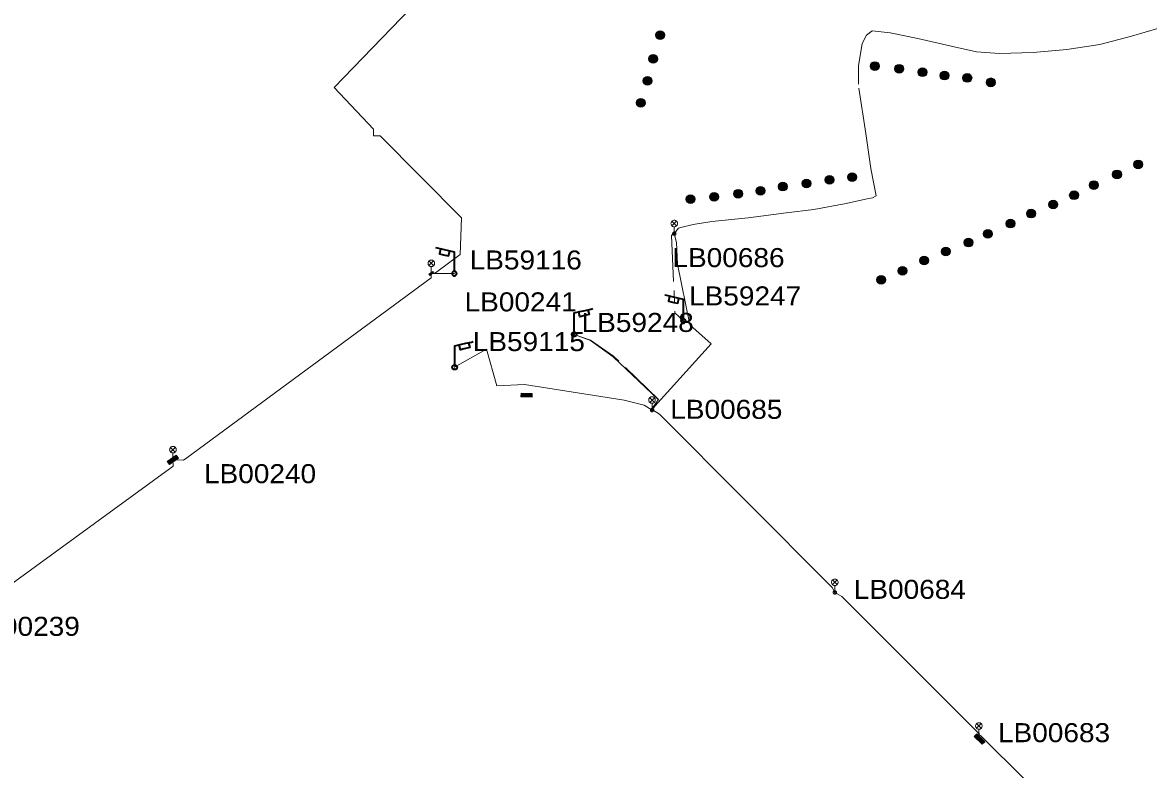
# Model space of a CAD drawing. Extents: x -688049 to -687261, y -973611 to -973038.
# Drawn here: x -687682.8 to -687554.6, y -973468.5 to -973383.4 of the extents above; entities that cross this region are included whole.
import ezdxf

# ---------------------------------------------------------------- set-up
doc = ezdxf.new("R2010")
doc.units = 0
doc.header["$LTSCALE"] = 0.87
doc.linetypes.add('LONG_DASH_SHORT_DASH', pattern=[9.9, 6, -1.2, 1.5, -1.2])
doc.linetypes.add('LONG_DASHED', pattern=[7.5, 6, -1.5])
doc.layers.add('1', color=7, linetype='Continuous', lineweight=13)

msp = doc.modelspace()

# ---------------------------------------------------------------- hatches: boundary and pattern name
at = {"layer": '1'}
for points in [[(-687610.051, -973385.316, 1), (-687610.35, -973384.372, 1)], [(-687610.844, -973388.007, 1), (-687611.143, -973387.063, 1)], [(-687585.608, -973388.841, 1), (-687585.907, -973387.896, 1)], [(-687582.831, -973389.138, 1), (-687583.13, -973388.194, 1)], [(-687580.194, -973389.545, 1), (-687580.493, -973388.601, 1)], [(-687577.677, -973389.928, 1), (-687577.976, -973388.984, 1)], [(-687575.088, -973390.19, 1), (-687575.387, -973389.246, 1)], [(-687611.485, -973390.519, 1), (-687611.784, -973389.574, 1)], [(-687572.426, -973390.694, 1), (-687572.725, -973389.749, 1)], [(-687612.25, -973393.017, 1), (-687612.549, -973392.072, 1)], [(-687555.641, -973400.036, 1), (-687555.94, -973399.092, 1)], [(-687590.78, -973401.793, 1), (-687591.079, -973400.849, 1)], [(-687588.186, -973401.491, 1), (-687588.485, -973400.546, 1)], [(-687558.051, -973401.176, 1), (-687558.35, -973400.232, 1)], [(-687598.621, -973403.047, 1), (-687598.92, -973402.103, 1)], [(-687596.084, -973402.573, 1), (-687596.382, -973401.628, 1)], [(-687593.401, -973402.217, 1), (-687593.699, -973401.273, 1)], [(-687560.679, -973402.389, 1), (-687560.978, -973401.444, 1)], [(-687606.599, -973403.992, 1), (-687606.898, -973403.047, 1)], [(-687603.915, -973403.733, 1), (-687604.214, -973402.789, 1)], [(-687601.184, -973403.377, 1), (-687601.483, -973402.433, 1)], [(-687562.944, -973403.558, 1), (-687563.243, -973402.613, 1)], [(-687567.837, -973405.645, 1), (-687568.136, -973404.701, 1)], [(-687565.306, -973404.601, 1), (-687565.605, -973403.657, 1)], [(-687570.175, -973406.785, 1), (-687570.474, -973405.841, 1)], [(-687572.754, -973407.949, 1), (-687573.053, -973407.005, 1)], [(-687574.948, -973408.945, 1), (-687575.246, -973408, 1)], [(-687577.527, -973409.966, 1), (-687577.826, -973409.021, 1)], [(-687580.008, -973410.99, 1), (-687580.307, -973410.046, 1)], [(-687635.974, -973411.887), (-687636.396, -973412.214), (-687636.505, -973412.073), (-687636.083, -973411.747)], [(-687636.102, -973411.896), (-687636.356, -973412.092), (-687636.377, -973412.064), (-687636.124, -973411.868)], [(-687584.892, -973413.189, 1), (-687585.191, -973412.245, 1)], [(-687582.471, -973412.165, 1), (-687582.77, -973411.221, 1)], [(-687624.773, -973426.072), (-687626.038, -973426.054), (-687626.032, -973425.632), (-687624.767, -973425.65)], [(-687625.024, -973425.9), (-687625.783, -973425.889), (-687625.782, -973425.805), (-687625.022, -973425.815)], [(-687665.014, -973433.008), (-687666.038, -973433.752), (-687666.286, -973433.411), (-687665.262, -973432.666)], [(-687665.318, -973433.02), (-687665.932, -973433.467), (-687665.982, -973433.398), (-687665.368, -973432.952)], [(-687574.161, -973464.421), (-687573.26, -973465.31), (-687573.556, -973465.61), (-687574.457, -973464.722)], [(-687574.099, -973464.719), (-687573.558, -973465.252), (-687573.618, -973465.312), (-687574.158, -973464.779)]]:
    msp.add_hatch(color=256, dxfattribs=at).paths.add_polyline_path(points)

# ---------------------------------------------------------------- linework, layer by layer
for p, q in [((-687608.855, -973406.035), (-687608.325, -973406.565)), ((-687608.855, -973406.565), (-687608.325, -973406.035)), ((-687608.59, -973407.45), (-687608.59, -973406.675)), ((-687636.505, -973410.565), (-687635.975, -973411.095)), ((-687636.505, -973411.095), (-687635.975, -973410.565)), ((-687636.24, -973411.98), (-687636.24, -973411.205)), ((-687611.385, -973426.135), (-687610.855, -973426.665)), ((-687611.385, -973426.665), (-687610.855, -973426.135)), ((-687611.12, -973427.55), (-687611.12, -973426.775)), ((-687665.915, -973431.795), (-687665.385, -973432.325)), ((-687665.915, -973432.325), (-687665.385, -973431.795)), ((-687665.65, -973433.21), (-687665.65, -973432.435)), ((-687590.585, -973446.895), (-687590.055, -973447.425)), ((-687590.585, -973447.425), (-687590.055, -973446.895)), ((-687590.32, -973448.31), (-687590.32, -973447.535)), ((-687574.185, -973463.255), (-687573.655, -973463.785)), ((-687574.185, -973463.785), (-687573.655, -973463.255)), ((-687573.92, -973464.67), (-687573.92, -973463.895))]:
    msp.add_line(p, q, dxfattribs=at)
at = {"layer": '1', "linetype": 'LONG_DASHED'}
msp.add_line((-687636.24, -973411.98), (-687633.616, -973411.993), dxfattribs=at)
at = {"layer": '1', "lineweight": 35}
for p, q in [((-687633.589, -973411.993), (-687633.643, -973411.993)), ((-687607.523, -973417.39), (-687607.577, -973417.39)), ((-687620.007, -973418.92), (-687619.953, -973418.92)), ((-687633.606, -973422.675), (-687633.552, -973422.675))]:
    msp.add_line(p, q, dxfattribs=at)
at = {"layer": '1'}
for points in [[(-687635.62, -973366.14), (-687635.225, -973365.919), (-687633.134, -973366.526), (-687636.395, -973379.478), (-687647.285, -973390.792), (-687642.829, -973395.545), (-687642.829, -973396.299), (-687642.074, -973396.299), (-687632.804, -973405.662), (-687632.954, -973409.811), (-687635.757, -973411.904), (-687636.24, -973411.98)], [(-687611.12, -973427.55), (-687610.797, -973427.086), (-687604.393, -973420.018), (-687606.807, -973417.83), (-687608.216, -973410.947), (-687608.337, -973408.473), (-687608.59, -973407.45)], [(-687636.24, -973411.98), (-687636.24, -973412.467), (-687664.079, -973432.966), (-687664.457, -973433.245), (-687665.65, -973433.21)], [(-687619.98, -973418.92), (-687618.115, -973419.615), (-687615.548, -973421.498), (-687610.435, -973426.34), (-687611.12, -973427.55)], [(-687611.12, -973427.55), (-687612.029, -973427.002), (-687614.309, -973426.435), (-687625.62, -973424.619), (-687628.769, -973424.779), (-687629.963, -973420.617), (-687633.597, -973422.675)], [(-687611.085, -973427.515), (-687610.257, -973428.003), (-687590.631, -973447.734), (-687590.299, -973448.319)], [(-687665.65, -973433.21), (-687665.607, -973433.919), (-687690.297, -973451.9), (-687691.35, -973452.06)], [(-687590.299, -973448.319), (-687589.534, -973448.773), (-687573.855, -973464.45), (-687573.92, -973464.67)], [(-687573.92, -973464.67), (-687573.727, -973464.6), (-687563.369, -973474.889), (-687563.105, -973476.008), (-687557.547, -973481.454), (-687555.888, -973481.862), (-687555.339, -973482.791), (-687555.04, -973483.62)]]:
    msp.add_lwpolyline(points, dxfattribs=at)
at = {"layer": '1', "linetype": 'LONG_DASH_SHORT_DASH'}
for points in [[(-687608.55, -973407.38), (-687608.11, -973406.84), (-687607.68, -973406.71), (-687606.43, -973406.41), (-687604.3, -973406.08), (-687600.18, -973405.65), (-687595.86, -973405.09), (-687592.69, -973404.71), (-687589.01, -973404.01), (-687586.83, -973403.53), (-687586.02, -973403.36), (-687585.62, -973403.15), (-687586.23, -973400.05), (-687586.8, -973396.04), (-687587.64, -973390.41), (-687587.64, -973388.33), (-687587.22, -973385.79), (-687586.71, -973384.83), (-687586.07, -973384.34), (-687584, -973384.57), (-687580.87, -973385.24), (-687577.06, -973386.09), (-687574.21, -973386.74), (-687571.58, -973386.94), (-687567.76, -973386.84), (-687563.92, -973386.49), (-687560.14, -973385.9), (-687556.57, -973384.95), (-687553.44, -973384.04)], [(-687608.61, -973407.33), (-687608.89, -973407.68), (-687608.51, -973416.47), (-687607.55, -973417.39)], [(-687611.15, -973427.39), (-687610.39, -973426.34), (-687615.5, -973421.39), (-687618.11, -973419.59), (-687619.98, -973418.92)]]:
    msp.add_lwpolyline(points, dxfattribs=at)
at = {"layer": '1'}
for points in [[(-687608.215, -973406.3), (-687608.221, -973406.235), (-687608.238, -973406.172), (-687608.265, -973406.112), (-687608.303, -973406.059), (-687608.349, -973406.013), (-687608.402, -973405.975), (-687608.462, -973405.948), (-687608.525, -973405.931), (-687608.59, -973405.925), (-687608.655, -973405.931), (-687608.718, -973405.948), (-687608.778, -973405.975), (-687608.831, -973406.013), (-687608.877, -973406.059), (-687608.915, -973406.112), (-687608.942, -973406.172), (-687608.959, -973406.235), (-687608.965, -973406.3), (-687608.959, -973406.365), (-687608.942, -973406.428), (-687608.915, -973406.487), (-687608.877, -973406.541), (-687608.831, -973406.587), (-687608.778, -973406.625), (-687608.718, -973406.652), (-687608.655, -973406.669), (-687608.59, -973406.675), (-687608.525, -973406.669), (-687608.462, -973406.652), (-687608.402, -973406.625), (-687608.349, -973406.587), (-687608.303, -973406.541), (-687608.265, -973406.487), (-687608.238, -973406.428), (-687608.221, -973406.365)], [(-687608.4, -973407.45), (-687608.403, -973407.417), (-687608.411, -973407.385), (-687608.425, -973407.355), (-687608.444, -973407.328), (-687608.468, -973407.304), (-687608.495, -973407.285), (-687608.525, -973407.271), (-687608.557, -973407.263), (-687608.59, -973407.26), (-687608.623, -973407.263), (-687608.655, -973407.271), (-687608.685, -973407.285), (-687608.712, -973407.304), (-687608.736, -973407.328), (-687608.755, -973407.355), (-687608.769, -973407.385), (-687608.777, -973407.417), (-687608.78, -973407.45), (-687608.777, -973407.483), (-687608.769, -973407.515), (-687608.755, -973407.545), (-687608.736, -973407.572), (-687608.712, -973407.596), (-687608.685, -973407.615), (-687608.655, -973407.629), (-687608.623, -973407.637), (-687608.59, -973407.64), (-687608.557, -973407.637), (-687608.525, -973407.629), (-687608.495, -973407.615), (-687608.468, -973407.596), (-687608.444, -973407.572), (-687608.425, -973407.545), (-687608.411, -973407.515), (-687608.403, -973407.483)], [(-687608.54, -973407.45), (-687608.541, -973407.441), (-687608.543, -973407.433), (-687608.547, -973407.425), (-687608.552, -973407.418), (-687608.558, -973407.412), (-687608.565, -973407.407), (-687608.573, -973407.403), (-687608.581, -973407.401), (-687608.59, -973407.4), (-687608.599, -973407.401), (-687608.607, -973407.403), (-687608.615, -973407.407), (-687608.622, -973407.412), (-687608.628, -973407.418), (-687608.633, -973407.425), (-687608.637, -973407.433), (-687608.639, -973407.441), (-687608.64, -973407.45), (-687608.639, -973407.459), (-687608.637, -973407.467), (-687608.633, -973407.475), (-687608.628, -973407.482), (-687608.622, -973407.488), (-687608.615, -973407.493), (-687608.607, -973407.497), (-687608.599, -973407.499), (-687608.59, -973407.5), (-687608.581, -973407.499), (-687608.573, -973407.497), (-687608.565, -973407.493), (-687608.558, -973407.488), (-687608.552, -973407.482), (-687608.547, -973407.475), (-687608.543, -973407.467), (-687608.541, -973407.459)], [(-687635.865, -973410.83), (-687635.871, -973410.765), (-687635.888, -973410.702), (-687635.915, -973410.643), (-687635.953, -973410.589), (-687635.999, -973410.543), (-687636.052, -973410.505), (-687636.112, -973410.478), (-687636.175, -973410.461), (-687636.24, -973410.455), (-687636.305, -973410.461), (-687636.368, -973410.478), (-687636.428, -973410.505), (-687636.481, -973410.543), (-687636.527, -973410.589), (-687636.565, -973410.643), (-687636.592, -973410.702), (-687636.609, -973410.765), (-687636.615, -973410.83), (-687636.609, -973410.895), (-687636.592, -973410.958), (-687636.565, -973411.018), (-687636.527, -973411.071), (-687636.481, -973411.117), (-687636.428, -973411.155), (-687636.368, -973411.182), (-687636.305, -973411.199), (-687636.24, -973411.205), (-687636.175, -973411.199), (-687636.112, -973411.182), (-687636.052, -973411.155), (-687635.999, -973411.117), (-687635.953, -973411.071), (-687635.915, -973411.018), (-687635.888, -973410.958), (-687635.871, -973410.895)], [(-687635.974, -973411.887), (-687636.396, -973412.214), (-687636.505, -973412.073), (-687636.083, -973411.747)], [(-687635.974, -973411.887), (-687636.396, -973412.214), (-687636.505, -973412.073), (-687636.083, -973411.747)], [(-687636.102, -973411.896), (-687636.356, -973412.092), (-687636.377, -973412.064), (-687636.124, -973411.868)], [(-687624.773, -973426.072), (-687626.038, -973426.054), (-687626.032, -973425.632), (-687624.767, -973425.65)], [(-687624.773, -973426.072), (-687626.038, -973426.054), (-687626.032, -973425.632), (-687624.767, -973425.65)], [(-687625.024, -973425.9), (-687625.783, -973425.889), (-687625.782, -973425.805), (-687625.022, -973425.815)], [(-687610.745, -973426.4), (-687610.751, -973426.335), (-687610.768, -973426.272), (-687610.795, -973426.212), (-687610.833, -973426.159), (-687610.879, -973426.113), (-687610.932, -973426.075), (-687610.992, -973426.048), (-687611.055, -973426.031), (-687611.12, -973426.025), (-687611.185, -973426.031), (-687611.248, -973426.048), (-687611.308, -973426.075), (-687611.361, -973426.113), (-687611.407, -973426.159), (-687611.445, -973426.212), (-687611.472, -973426.272), (-687611.489, -973426.335), (-687611.495, -973426.4), (-687611.489, -973426.465), (-687611.472, -973426.528), (-687611.445, -973426.588), (-687611.407, -973426.641), (-687611.361, -973426.687), (-687611.308, -973426.725), (-687611.248, -973426.752), (-687611.185, -973426.769), (-687611.12, -973426.775), (-687611.055, -973426.769), (-687610.992, -973426.752), (-687610.932, -973426.725), (-687610.879, -973426.687), (-687610.833, -973426.641), (-687610.795, -973426.588), (-687610.768, -973426.528), (-687610.751, -973426.465)], [(-687610.93, -973427.55), (-687610.933, -973427.517), (-687610.941, -973427.485), (-687610.955, -973427.455), (-687610.974, -973427.428), (-687610.998, -973427.404), (-687611.025, -973427.385), (-687611.055, -973427.371), (-687611.087, -973427.363), (-687611.12, -973427.36), (-687611.153, -973427.363), (-687611.185, -973427.371), (-687611.215, -973427.385), (-687611.242, -973427.404), (-687611.266, -973427.428), (-687611.285, -973427.455), (-687611.299, -973427.485), (-687611.307, -973427.517), (-687611.31, -973427.55), (-687611.307, -973427.583), (-687611.299, -973427.615), (-687611.285, -973427.645), (-687611.266, -973427.672), (-687611.242, -973427.696), (-687611.215, -973427.715), (-687611.185, -973427.729), (-687611.153, -973427.737), (-687611.12, -973427.74), (-687611.087, -973427.737), (-687611.055, -973427.729), (-687611.025, -973427.715), (-687610.998, -973427.696), (-687610.974, -973427.672), (-687610.955, -973427.645), (-687610.941, -973427.615), (-687610.933, -973427.583)], [(-687611.07, -973427.55), (-687611.071, -973427.541), (-687611.073, -973427.533), (-687611.077, -973427.525), (-687611.082, -973427.518), (-687611.088, -973427.512), (-687611.095, -973427.507), (-687611.103, -973427.503), (-687611.111, -973427.501), (-687611.12, -973427.5), (-687611.129, -973427.501), (-687611.137, -973427.503), (-687611.145, -973427.507), (-687611.152, -973427.512), (-687611.158, -973427.518), (-687611.163, -973427.525), (-687611.167, -973427.533), (-687611.169, -973427.541), (-687611.17, -973427.55), (-687611.169, -973427.559), (-687611.167, -973427.567), (-687611.163, -973427.575), (-687611.158, -973427.582), (-687611.152, -973427.588), (-687611.145, -973427.593), (-687611.137, -973427.597), (-687611.129, -973427.599), (-687611.12, -973427.6), (-687611.111, -973427.599), (-687611.103, -973427.597), (-687611.095, -973427.593), (-687611.088, -973427.588), (-687611.082, -973427.582), (-687611.077, -973427.575), (-687611.073, -973427.567), (-687611.071, -973427.559)], [(-687665.014, -973433.008), (-687666.038, -973433.752), (-687666.286, -973433.411), (-687665.262, -973432.666)], [(-687665.014, -973433.008), (-687666.038, -973433.752), (-687666.286, -973433.411), (-687665.262, -973432.666)], [(-687665.275, -973432.06), (-687665.281, -973431.995), (-687665.298, -973431.932), (-687665.325, -973431.872), (-687665.363, -973431.819), (-687665.409, -973431.773), (-687665.462, -973431.735), (-687665.522, -973431.708), (-687665.585, -973431.691), (-687665.65, -973431.685), (-687665.715, -973431.691), (-687665.778, -973431.708), (-687665.838, -973431.735), (-687665.891, -973431.773), (-687665.937, -973431.819), (-687665.975, -973431.872), (-687666.002, -973431.932), (-687666.019, -973431.995), (-687666.025, -973432.06), (-687666.019, -973432.125), (-687666.002, -973432.188), (-687665.975, -973432.247), (-687665.937, -973432.301), (-687665.891, -973432.347), (-687665.838, -973432.385), (-687665.778, -973432.412), (-687665.715, -973432.429), (-687665.65, -973432.435), (-687665.585, -973432.429), (-687665.522, -973432.412), (-687665.462, -973432.385), (-687665.409, -973432.347), (-687665.363, -973432.301), (-687665.325, -973432.247), (-687665.298, -973432.188), (-687665.281, -973432.125)], [(-687665.318, -973433.02), (-687665.932, -973433.467), (-687665.982, -973433.398), (-687665.368, -973432.952)], [(-687589.945, -973447.16), (-687589.951, -973447.095), (-687589.968, -973447.032), (-687589.995, -973446.972), (-687590.033, -973446.919), (-687590.079, -973446.873), (-687590.133, -973446.835), (-687590.192, -973446.808), (-687590.255, -973446.791), (-687590.32, -973446.785), (-687590.385, -973446.791), (-687590.448, -973446.808), (-687590.508, -973446.835), (-687590.561, -973446.873), (-687590.607, -973446.919), (-687590.645, -973446.972), (-687590.672, -973447.032), (-687590.689, -973447.095), (-687590.695, -973447.16), (-687590.689, -973447.225), (-687590.672, -973447.288), (-687590.645, -973447.348), (-687590.607, -973447.401), (-687590.561, -973447.447), (-687590.508, -973447.485), (-687590.448, -973447.512), (-687590.385, -973447.529), (-687590.32, -973447.535), (-687590.255, -973447.529), (-687590.192, -973447.512), (-687590.133, -973447.485), (-687590.079, -973447.447), (-687590.033, -973447.401), (-687589.995, -973447.348), (-687589.968, -973447.288), (-687589.951, -973447.225)], [(-687590.13, -973448.31), (-687590.133, -973448.277), (-687590.141, -973448.245), (-687590.155, -973448.215), (-687590.174, -973448.188), (-687590.198, -973448.164), (-687590.225, -973448.145), (-687590.255, -973448.131), (-687590.287, -973448.123), (-687590.32, -973448.12), (-687590.353, -973448.123), (-687590.385, -973448.131), (-687590.415, -973448.145), (-687590.442, -973448.164), (-687590.466, -973448.188), (-687590.485, -973448.215), (-687590.499, -973448.245), (-687590.507, -973448.277), (-687590.51, -973448.31), (-687590.507, -973448.343), (-687590.499, -973448.375), (-687590.485, -973448.405), (-687590.466, -973448.432), (-687590.442, -973448.456), (-687590.415, -973448.475), (-687590.385, -973448.489), (-687590.353, -973448.497), (-687590.32, -973448.5), (-687590.287, -973448.497), (-687590.255, -973448.489), (-687590.225, -973448.475), (-687590.198, -973448.456), (-687590.174, -973448.432), (-687590.155, -973448.405), (-687590.141, -973448.375), (-687590.133, -973448.343)], [(-687590.27, -973448.31), (-687590.271, -973448.301), (-687590.273, -973448.293), (-687590.277, -973448.285), (-687590.282, -973448.278), (-687590.288, -973448.272), (-687590.295, -973448.267), (-687590.303, -973448.263), (-687590.311, -973448.261), (-687590.32, -973448.26), (-687590.329, -973448.261), (-687590.337, -973448.263), (-687590.345, -973448.267), (-687590.352, -973448.272), (-687590.358, -973448.278), (-687590.363, -973448.285), (-687590.367, -973448.293), (-687590.369, -973448.301), (-687590.37, -973448.31), (-687590.369, -973448.319), (-687590.367, -973448.327), (-687590.363, -973448.335), (-687590.358, -973448.342), (-687590.352, -973448.348), (-687590.345, -973448.353), (-687590.337, -973448.357), (-687590.329, -973448.359), (-687590.32, -973448.36), (-687590.311, -973448.359), (-687590.303, -973448.357), (-687590.295, -973448.353), (-687590.288, -973448.348), (-687590.282, -973448.342), (-687590.277, -973448.335), (-687590.273, -973448.327), (-687590.271, -973448.319)], [(-687573.545, -973463.52), (-687573.551, -973463.455), (-687573.568, -973463.392), (-687573.595, -973463.332), (-687573.633, -973463.279), (-687573.679, -973463.233), (-687573.732, -973463.195), (-687573.792, -973463.168), (-687573.855, -973463.151), (-687573.92, -973463.145), (-687573.985, -973463.151), (-687574.048, -973463.168), (-687574.108, -973463.195), (-687574.161, -973463.233), (-687574.207, -973463.279), (-687574.245, -973463.332), (-687574.272, -973463.392), (-687574.289, -973463.455), (-687574.295, -973463.52), (-687574.289, -973463.585), (-687574.272, -973463.648), (-687574.245, -973463.708), (-687574.207, -973463.761), (-687574.161, -973463.807), (-687574.108, -973463.845), (-687574.048, -973463.872), (-687573.985, -973463.889), (-687573.92, -973463.895), (-687573.855, -973463.889), (-687573.792, -973463.872), (-687573.732, -973463.845), (-687573.679, -973463.807), (-687573.633, -973463.761), (-687573.595, -973463.708), (-687573.568, -973463.648), (-687573.551, -973463.585)], [(-687574.161, -973464.421), (-687573.26, -973465.31), (-687573.556, -973465.61), (-687574.457, -973464.722)], [(-687574.161, -973464.421), (-687573.26, -973465.31), (-687573.556, -973465.61), (-687574.457, -973464.722)], [(-687574.099, -973464.719), (-687573.558, -973465.252), (-687573.618, -973465.312), (-687574.158, -973464.779)]]:
    msp.add_lwpolyline(points, close=True, dxfattribs=at)
at = {"layer": '1', "lineweight": 35}
for points in [[(-687633.616, -973411.738), (-687633.703, -973411.738), (-687633.838, -973411.836), (-687633.892, -973411.993), (-687633.838, -973412.15), (-687633.703, -973412.248), (-687633.535, -973412.248), (-687633.399, -973412.15), (-687633.345, -973411.993), (-687633.399, -973411.836), (-687633.535, -973411.738), (-687633.616, -973411.738), (-687633.616, -973411.05), (-687633.616, -973410.362), (-687633.616, -973409.674), (-687633.616, -973409.555), (-687634.25, -973409.408), (-687634.884, -973409.262), (-687635.518, -973409.116), (-687635.729, -973409.067)], [(-687635.187, -973409.202), (-687635.323, -973409.744), (-687634.689, -973409.891), (-687634.266, -973409.988), (-687634.131, -973409.446)], [(-687607.55, -973417.135), (-687607.637, -973417.135), (-687607.772, -973417.233), (-687607.826, -973417.39), (-687607.772, -973417.547), (-687607.637, -973417.645), (-687607.469, -973417.645), (-687607.333, -973417.547), (-687607.279, -973417.39), (-687607.333, -973417.233), (-687607.469, -973417.135), (-687607.55, -973417.135), (-687607.55, -973416.447), (-687607.55, -973415.759), (-687607.55, -973415.071), (-687607.55, -973414.952), (-687608.184, -973414.805), (-687608.818, -973414.659), (-687609.452, -973414.513), (-687609.663, -973414.464)], [(-687609.121, -973414.599), (-687609.257, -973415.141), (-687608.623, -973415.288), (-687608.2, -973415.385), (-687608.065, -973414.843)], [(-687619.98, -973418.665), (-687619.893, -973418.665), (-687619.758, -973418.763), (-687619.704, -973418.92), (-687619.758, -973419.077), (-687619.893, -973419.175), (-687620.061, -973419.175), (-687620.197, -973419.077), (-687620.251, -973418.92), (-687620.197, -973418.763), (-687620.061, -973418.665), (-687619.98, -973418.665), (-687619.98, -973417.977), (-687619.98, -973417.289), (-687619.98, -973416.601), (-687619.98, -973416.482), (-687619.346, -973416.335), (-687618.712, -973416.189), (-687618.078, -973416.043), (-687617.867, -973415.994)], [(-687618.409, -973416.129), (-687618.273, -973416.671), (-687618.907, -973416.818), (-687619.33, -973416.915), (-687619.465, -973416.373)], [(-687633.579, -973422.42), (-687633.492, -973422.42), (-687633.357, -973422.518), (-687633.303, -973422.675), (-687633.357, -973422.832), (-687633.492, -973422.93), (-687633.66, -973422.93), (-687633.796, -973422.832), (-687633.85, -973422.675), (-687633.796, -973422.518), (-687633.66, -973422.42), (-687633.579, -973422.42), (-687633.579, -973421.732), (-687633.579, -973421.044), (-687633.579, -973420.356), (-687633.579, -973420.237), (-687632.945, -973420.09), (-687632.311, -973419.944), (-687631.677, -973419.798), (-687631.466, -973419.749)], [(-687632.008, -973419.884), (-687631.872, -973420.426), (-687632.506, -973420.573), (-687632.929, -973420.67), (-687633.064, -973420.128)]]:
    msp.add_lwpolyline(points, dxfattribs=at)
at = {"layer": '1', "lineweight": 25}
for centre in [(-687610.201, -973384.844), (-687610.993, -973387.535), (-687585.758, -973388.368), (-687582.98, -973388.666), (-687580.343, -973389.073), (-687577.826, -973389.456), (-687575.237, -973389.718), (-687611.634, -973390.047), (-687572.576, -973390.221), (-687612.399, -973392.544), (-687555.791, -973399.564), (-687590.929, -973401.321), (-687588.335, -973401.019), (-687558.201, -973400.704), (-687598.77, -973402.575), (-687596.233, -973402.1), (-687593.55, -973401.745), (-687560.828, -973401.917), (-687606.748, -973403.519), (-687604.064, -973403.261), (-687601.333, -973402.905), (-687563.094, -973403.086), (-687567.987, -973405.173), (-687565.456, -973404.129), (-687570.325, -973406.313), (-687572.904, -973407.477), (-687575.097, -973408.473), (-687577.676, -973409.493), (-687580.158, -973410.518), (-687585.042, -973412.717), (-687582.62, -973411.693)]:
    msp.add_circle(centre, 0.495, dxfattribs=at)

# ---------------------------------------------------------------- texts
at = {"layer": '1', "width": 1.1}
for s, height, p in [('LB59116', 2.167, (-687631.876, -973411.534)), ('LB00686', 2.167, (-687608.797, -973411.264)), ('LB59247', 2.168, (-687606.909, -973415.627)), ('LB00241', 2.167, (-687632.455, -973416.306)), ('LB59248', 2.168, (-687619.138, -973418.647)), ('LB59115', 2.167, (-687631.524, -973420.828)), ('LB00685', 2.167, (-687609.049, -973428.542)), ('LB00240', 2.167, (-687662.114, -973435.871)), ('LB00684', 2.167, (-687588.159, -973449.046)), ('LB00239', 2.167, (-687689.004, -973453.257)), ('LB00683', 2.167, (-687571.748, -973465.367))]:
    msp.add_text(s, height=height, dxfattribs=at).set_placement(p)

doc.saveas('drawing.dxf')
